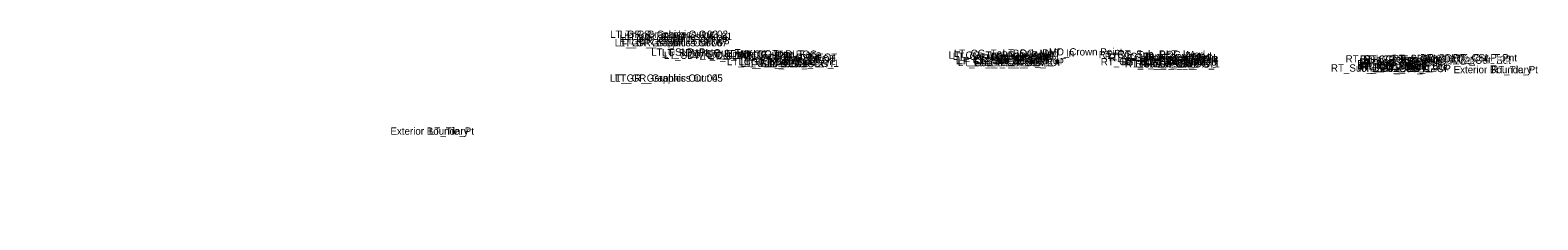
# Model space of a CAD drawing. Extents: x -26 to 6300, y -10 to 9528.
# Drawn here: x 1000 to 1206.6, y 0 to 26 of the extents above; entities that cross this region are included whole.
import ezdxf

# ---------------------------------------------------------------- set-up
doc = ezdxf.new("R2010")
doc.units = 0
doc.layers.add('Default', color=7, linetype='Continuous')

msp = doc.modelspace()

# ---------------------------------------------------------------- texts
at = {"layer": 'Default'}
for s, height, p in [('LT_GR_Graphics Out 03', 1, (1079.47, 24.91)), ('LT_GR_Graphics Out 06', 1, (1080.11, 23.75)), ('LT_GR_Graphics Out 07', 1, (1080.75, 23.75)), ('LT_GR_Graphics Out 09', 1, (1080.78, 24.33)), ('LT_GR_Graphics Out 02', 1, (1080.83, 24.91)), ('LT_GR_Graphics Out 08', 1, (1081.04, 24.04)), ('LT_GR_Graphics Out 01', 1, (1081.39, 24.62)), ('LT_CSLP_Pnt', 1, (1085.1, 22.47)), ('LT_SDWK_Out_Top', 1, (1086.58, 22.37)), ('LT_SDWK_Out_Bot', 1, (1086.83, 22.04)), ('LT_Sub_Trench_Out_DLT', 1, (1090.25, 22.22)), ('LT_SDWK_In_Top', 1, (1092.74, 22.27)), ('LT_SDWK_In_Bot', 1, (1092.99, 21.94)), ('LT_CG_Top_BOC', 1, (1096.81, 22.18)), ('LT_CG_Top_Face', 1, (1097.34, 22.18)), ('LT_PV1_OEOT', 1, (1101.23, 21.77)), ('LT_CG_Top_Face_Med', 1, (1125.87, 22.05)), ('LT_CG_Top_Gut_Med', 1, (1126.42, 21.89)), ('LT_CG_Top_BOC_Med', 1, (1126.57, 22.3)), ('LT_PV1_PGL', 1, (1131.5, 21.89)), ('LT_Sub_DLT_In', 1, (1133.25, 22.35)), ('MD_Crown Point', 1, (1139.58, 22.5)), ('RT_CG_Top_BOC_Med', 1, (1146.43, 22.13)), ('RT_CG_Top_Face_Med', 1, (1147.25, 21.88)), ('RT_CG_Top_Gut_Med', 1, (1147.8, 21.72)), ('RT_Sub_DLT_In', 1, (1149.03, 22.21)), ('LT_CG1_Shelf_Out', 1, (1095.48, 21.17)), ('LT_CG_Bot_BOC', 1, (1097.09, 21.17)), ('LT_Sub_OEOT_CG_1', 1, (1097.36, 20.93)), ('LT_Sub_OEOP', 1, (1097.78, 20.92)), ('LT_CG_Top_Gut', 1, (1097.87, 21.68)), ('LT_PV2_OEOT', 1, (1100.99, 21.52)), ('LT_PV3_OEOT', 1, (1100.99, 21.27)), ('LT_Sub_OEOT', 1, (1101.04, 20.89)), ('LT_CG_Bot_IE', 1, (1101.34, 21.18)), ('LT_CG_Bot_BOC_Med', 1, (1126.85, 21.31)), ('LT_CG_Bot_IE_Med', 1, (1127.09, 21.3)), ('LT_Sub_IEOT_CG_1', 1, (1127.13, 21.05)), ('LT_PV2_OEEOP', 1, (1129.29, 21.64)), ('LT_PV3_OEEOP', 1, (1129.29, 21.39)), ('LT_Sub_OEEOP', 1, (1129.33, 21.01)), ('LT_PV2_IEEOP', 1, (1130.05, 21.64)), ('LT_Sub_IEEOP', 1, (1130.09, 21.01)), ('LT_CG1_Shelf_In', 1, (1130.71, 21.31)), ('LT_PV2_PGL', 1, (1131.26, 21.64)), ('LT_Sub_PGL', 1, (1131.31, 21.01)), ('LT_Sub_IEOP', 1, (1133.05, 21.06)), ('RT_CG_Bot_BOC_Med', 1, (1146.71, 21.15)), ('RT_CG1_Shelf_In', 1, (1149.57, 21.16)), ('RT_CG_Bot_IE_Med', 1, (1149.98, 21.12)), ('RT_Sub_IEOT_CG_1', 1, (1150.01, 20.87)), ('RT_Sub_IEOP', 1, (1151.42, 20.91)), ('RT_PV2_OEEOP', 1, (1152.17, 21.45)), ('RT_PV3_OEEOP', 1, (1152.17, 21.2)), ('RT_Sub_OEEOP', 1, (1152.21, 20.83)), ('RT_PV2_IEEOP', 1, (1152.93, 21.45)), ('RT_Sub_IEEOP', 1, (1152.97, 20.83)), ('RT_PV2_PGL', 1, (1154.15, 21.45)), ('RT_Sub_PGL', 1, (1154.19, 20.83)), ('RT_PV1_PGL', 1, (1154.38, 21.7)), ('RT_Sub_OEOT_CG_1', 1, (1178.25, 20.29)), ('RT_Sub_Trench_Out_DLT', 1, (1180.26, 21.54)), ('RT_PV2_OEOT', 1, (1181.87, 20.87)), ('RT_PV3_OEOT', 1, (1181.87, 20.62)), ('RT_Sub_OEOT', 1, (1181.92, 20.25)), ('RT_PV1_OEOT', 1, (1182.11, 21.12)), ('RT_CG_Top_Face', 1, (1182.22, 21.5)), ('RT_CG_Bot_IE', 1, (1182.22, 20.54)), ('RT_CG1_Shelf_Out', 1, (1182.36, 20.48)), ('RT_CG_Top_BOC', 1, (1182.69, 21.5)), ('RT_CG_Top_Gut', 1, (1182.75, 21)), ('RT_CG_Bot_BOC', 1, (1182.97, 20.49)), ('RT_Sub_OEOP', 1, (1185.17, 20.22)), ('RT_SDWK_In_Top', 1, (1186.62, 21.59)), ('RT_SDWK_In_Bot', 1, (1186.87, 21.26)), ('RT_SDWK_Out_Top', 1, (1190.46, 21.69)), ('RT_SDWK_Out_Bot', 1, (1190.71, 21.36)), ('RT_CSLP_Pnt', 1, (1194.98, 21.69)), ('Exterior Boundary', 1, (1195.06, 20.07)), ('RT_Tie_Pt', 1, (1200.22, 20.07)), ('LT_GR_Graphics Out 04', 1, (1079.43, 18.91)), ('LT_GR_Graphics Out 05', 1, (1080.12, 18.91)), ('Exterior Boundary', 1, (1049.37, 11.65)), ('LT_Tie_Pt', 1, (1054.65, 11.65)), ('-', 0.0001, (1000, 0))]:
    msp.add_text(s, height=height, dxfattribs=at).set_placement(p)

doc.saveas('drawing.dxf')
